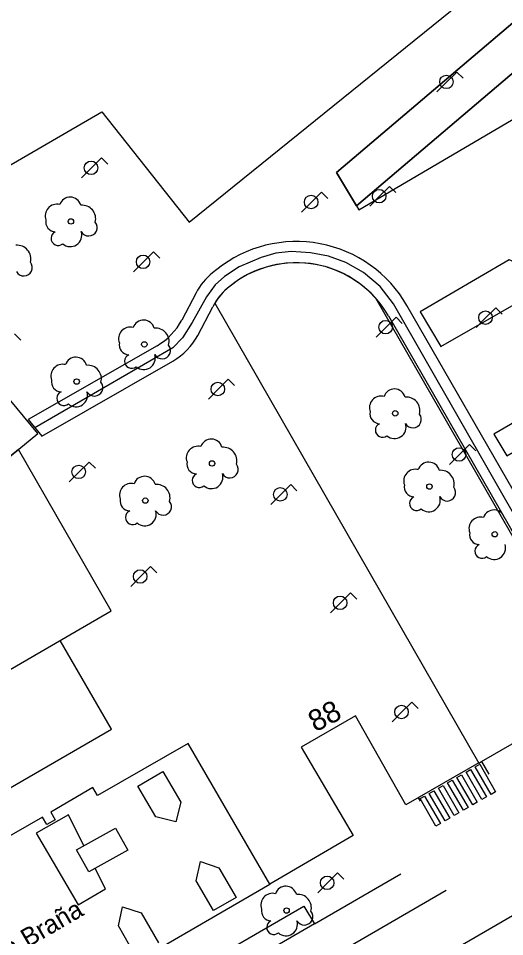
# Model space of a CAD drawing. Extents: x 282771 to 285132, y 4823109 to 4825496.
# Drawn here: x 283637.2 to 283683, y 4823709.7 to 4823796.3 of the extents above; entities that cross this region are included whole.
import ezdxf

# ---------------------------------------------------------------- set-up
doc = ezdxf.new("R2010")
doc.units = 0
for name, color, linetype in [('ACERA-BORDILLO', 7, 'Continuous'), ('ACERA-INTERIOR', 7, 'Continuous'), ('ARBOL', 7, 'Continuous'), ('CALLE-EJE', 7, 'Continuous'), ('CARRIL-BICI-AREA', 7, 'Continuous'), ('CARRIL-BICI-EJE', 7, 'Continuous'), ('EDIFICIO', 7, 'Continuous'), ('FAROLA', 7, 'Continuous'), ('MEDIANERA', 7, 'Continuous'), ('NUM-VADO', 7, 'Continuous'), ('PASO-PEATONES', 7, 'Continuous'), ('PUENTE', 7, 'Continuous'), ('SENAL-VIARIA', 7, 'Continuous'), ('TXT-EDIFICIOS', 7, 'Continuous'), ('ZONA-VERDE', 7, 'Continuous')]:
    doc.layers.add(name, color=color, linetype=linetype)

msp = doc.modelspace()

# ---------------------------------------------------------------- linework, layer by layer
at = {"layer": 'ACERA-BORDILLO'}
for points in [[(283680.803, 4823726.257), (283681.498, 4823725.059)], [(283674.845, 4823722.833), (283675.032, 4823722.51)], [(283440.639, 4823580.325), (283442.766, 4823581.559), (283443.123, 4823584.197), (283443.551, 4823584.826), (283531.38, 4823635.754), (283532.587, 4823633.905), (283540.184, 4823638.45), (283540.235, 4823640.838), (283664.058, 4823712.607), (283665.078, 4823710.943), (283673.217, 4823715.676)]]:
    msp.add_lwpolyline(points, dxfattribs=at)
at = {"layer": 'ACERA-INTERIOR'}
for points in [[(283604.679, 4823764.091), (283645.045, 4823787.52), (283653.258, 4823777.124), (283681.308, 4823799.827), (283702.664, 4823818.433), (283714.124, 4823828.582), (283725.715, 4823837.783), (283799.695, 4823901.125), (283801.01, 4823899.667), (283806.646, 4823904.515), (283805.178, 4823906.015), (283808.042, 4823908.37), (283805.528, 4823911.212), (283808.053, 4823913.515), (283807.084, 4823914.515), (283815.151, 4823921.216), (283815.364, 4823921.378), (283815.599, 4823921.524), (283815.853, 4823921.652), (283816.126, 4823921.757), (283816.413, 4823921.836), (283812.586, 4823926.094)], [(283606.699, 4823706.576), (283645.96, 4823729.307), (283641.115, 4823737.675)], [(283680.564, 4823726.129), (283673.691, 4823722.168), (283668.944, 4823730.574), (283663.817, 4823727.62), (283668.713, 4823719.274), (283660.862, 4823714.71)]]:
    msp.add_lwpolyline(points, dxfattribs=at)
at = {"layer": 'ARBOL'}
for centre in [(283642.123, 4823777.193), (283649.041, 4823765.603), (283642.663, 4823762.099), (283672.676, 4823759.099), (283655.42, 4823754.372), (283675.902, 4823752.197), (283649.131, 4823750.869), (283682.054, 4823747.695), (283662.444, 4823712.205)]:
    msp.add_circle(centre, 0.255, dxfattribs=at)
for centre, radius, start, end in [((283642.053, 4823778.453), 1.038, 15.64225, 161.38431), ((283640.793, 4823777.723), 1.097, 75.43176, 200.55605), ((283643.183, 4823777.453), 1.272, 345.0327, 95.79922), ((283640.683, 4823777.153), 0.935, 168.59894, 268.13232), ((283643.793, 4823776.623), 0.797, 208.96243, 38.99099), ((283640.923, 4823775.603), 0.672, 113.73669, 309.47246), ((283642.063, 4823775.903), 1.086, 228.95444, 17.92792), ((283637.074, 4823773.679), 1.272, 345.0327, 95.79922), ((283637.684, 4823772.849), 0.797, 208.96243, 38.99099), ((283648.971, 4823766.863), 1.038, 15.64225, 161.38431), ((283647.711, 4823766.133), 1.097, 75.43176, 200.55605), ((283650.101, 4823765.863), 1.272, 345.0327, 95.79922), ((283647.601, 4823765.563), 0.935, 168.59894, 268.13232), ((283650.711, 4823765.033), 0.797, 208.96243, 38.99099), ((283642.593, 4823763.359), 1.038, 15.64225, 161.38431), ((283647.841, 4823764.013), 0.672, 113.73669, 309.47246), ((283648.981, 4823764.313), 1.086, 228.95444, 17.92792), ((283641.333, 4823762.629), 1.097, 75.43176, 200.55605), ((283643.723, 4823762.359), 1.272, 345.0327, 95.79922), ((283641.223, 4823762.059), 0.935, 168.59894, 268.13232), ((283644.333, 4823761.529), 0.797, 208.96243, 38.99099), ((283672.606, 4823760.359), 1.038, 15.64225, 161.38431), ((283641.463, 4823760.509), 0.672, 113.73669, 309.47246), ((283642.603, 4823760.809), 1.086, 228.95444, 17.92792), ((283671.346, 4823759.629), 1.097, 75.43176, 200.55605), ((283673.736, 4823759.359), 1.272, 345.0327, 95.79922), ((283671.236, 4823759.059), 0.935, 168.59894, 268.13232), ((283674.346, 4823758.529), 0.797, 208.96243, 38.99099), ((283671.476, 4823757.509), 0.672, 113.73669, 309.47246), ((283672.616, 4823757.809), 1.086, 228.95444, 17.92792), ((283655.35, 4823755.632), 1.038, 15.64225, 161.38431), ((283654.09, 4823754.902), 1.097, 75.43176, 200.55605), ((283656.48, 4823754.632), 1.272, 345.0327, 95.79922), ((283653.98, 4823754.332), 0.935, 168.59894, 268.13232), ((283657.09, 4823753.802), 0.797, 208.96243, 38.99099), ((283675.832, 4823753.457), 1.038, 15.64225, 161.38431), ((283655.36, 4823753.082), 1.086, 228.95444, 17.92792), ((283674.572, 4823752.727), 1.097, 75.43176, 200.55605), ((283676.962, 4823752.457), 1.272, 345.0327, 95.79922), ((283649.061, 4823752.129), 1.038, 15.64225, 161.38431), ((283654.22, 4823752.782), 0.672, 113.73669, 309.47246), ((283647.801, 4823751.399), 1.097, 75.43176, 200.55605), ((283650.191, 4823751.129), 1.272, 345.0327, 95.79922), ((283674.462, 4823752.157), 0.935, 168.59894, 268.13232), ((283677.572, 4823751.627), 0.797, 208.96243, 38.99099), ((283647.691, 4823750.829), 0.935, 168.59894, 268.13232), ((283674.702, 4823750.607), 0.672, 113.73669, 309.47246), ((283675.842, 4823750.907), 1.086, 228.95444, 17.92792), ((283650.801, 4823750.299), 0.797, 208.96243, 38.99099), ((283681.984, 4823748.955), 1.038, 15.64225, 161.38431), ((283647.931, 4823749.279), 0.672, 113.73669, 309.47246), ((283649.071, 4823749.579), 1.086, 228.95444, 17.92792), ((283680.724, 4823748.225), 1.097, 75.43176, 200.55605), ((283680.614, 4823747.655), 0.935, 168.59894, 268.13232), ((283680.854, 4823746.105), 0.672, 113.73669, 309.47246), ((283681.994, 4823746.405), 1.086, 228.95444, 17.92792), ((283662.374, 4823713.465), 1.038, 15.64228, 161.38435), ((283661.114, 4823712.735), 1.097, 75.4318, 200.55608), ((283663.504, 4823712.465), 1.272, 345.03273, 95.79925), ((283661.004, 4823712.165), 0.935, 168.59898, 268.13236), ((283664.114, 4823711.635), 0.797, 208.96246, 38.99103), ((283661.244, 4823710.615), 0.672, 113.73672, 309.4725), ((283662.384, 4823710.915), 1.086, 228.95447, 17.92796)]:
    msp.add_arc(centre, radius, start, end, dxfattribs=at)
at = {"layer": 'CALLE-EJE'}
msp.add_lwpolyline([(283529.623, 4823622.259), (283685.293, 4823712.647)], dxfattribs=at)
at = {"layer": 'CARRIL-BICI-AREA'}
for p, q in [((283655.867, 4823772.67), (283655.472, 4823772.352)), ((283653.909, 4823770.455), (283652.569, 4823767.897)), ((283654.07, 4823766.452), (283655.487, 4823769.157)), ((283696.721, 4823729.269), (283673.783, 4823769.275)), ((283672.048, 4823768.28), (283694.991, 4823728.265)), ((283650.239, 4823765.477), (283638.082, 4823758.507)), ((283639.373, 4823756.941), (283651.74, 4823764.032)), ((283638.082, 4823758.507), (283639.373, 4823756.941))]:
    msp.add_line(p, q, dxfattribs=at)
msp.add_lwpolyline([(283657.049, 4823771.053), (283657.118, 4823771.109)], dxfattribs=at)
for centre, radius, start, end in [((283663.372, 4823763.306), 12, 29.82884, 128.71301), ((283663.372, 4823763.306), 10, 29.82884, 128.71301), ((283659.224, 4823767.671), 6, 128.71301, 152.3451), ((283660.801, 4823766.372), 6, 128.71301, 152.3451), ((283647.254, 4823770.682), 6, 299.8288, 332.3451), ((283648.755, 4823769.237), 6, 299.8288, 332.3451)]:
    msp.add_arc(centre, radius, start, end, dxfattribs=at)
at = {"layer": 'CARRIL-BICI-EJE'}
msp.add_lwpolyline([(283706.223, 4823710.47), (283672.517, 4823769.438), (283671.255, 4823771.052), (283669.683, 4823772.367), (283668.028, 4823773.312), (283666.405, 4823773.92), (283664.701, 4823774.239), (283662.886, 4823774.376), (283661.438, 4823774.202), (283660.033, 4823773.811), (283657.989, 4823772.922), (283656.6, 4823772.005), (283655.722, 4823771.223), (283654.884, 4823770.093), (283653.543, 4823767.672), (283652.632, 4823766.219), (283651.712, 4823765.287), (283638.727, 4823757.725)], dxfattribs=at)
at = {"layer": 'EDIFICIO'}
msp.add_lwpolyline([(283604.186, 4823681.769), (283660.862, 4823714.71), (283653.184, 4823727.954), (283644.633, 4823723.051), (283644.203, 4823723.801), (283640.223, 4823721.481), (283640.643, 4823720.761), (283639.843, 4823720.311), (283639.443, 4823721.021), (283635.463, 4823718.731)], dxfattribs=at)
at = {"layer": 'FAROLA'}
for p, q in [((283678.483, 4823791.287), (283677.543, 4823790.357)), ((283679.073, 4823790.697), (283678.483, 4823791.287)), ((283677.543, 4823790.357), (283676.613, 4823789.417)), ((283645.002, 4823783.186), (283644.062, 4823782.256)), ((283645.592, 4823782.596), (283645.002, 4823783.186)), ((283644.062, 4823782.256), (283643.132, 4823781.316)), ((283672.143, 4823780.507), (283671.203, 4823779.577)), ((283672.733, 4823779.917), (283672.143, 4823780.507)), ((283665.733, 4823779.957), (283664.793, 4823779.027)), ((283666.323, 4823779.367), (283665.733, 4823779.957)), ((283671.203, 4823779.577), (283670.273, 4823778.637)), ((283664.793, 4823779.027), (283663.863, 4823778.087)), ((283649.903, 4823774.317), (283648.963, 4823773.387)), ((283650.493, 4823773.727), (283649.903, 4823774.317)), ((283648.963, 4823773.387), (283648.033, 4823772.447)), ((283682.163, 4823769.057), (283681.223, 4823768.127)), ((283682.753, 4823768.467), (283682.163, 4823769.057)), ((283672.753, 4823768.157), (283671.813, 4823767.227)), ((283673.343, 4823767.567), (283672.753, 4823768.157)), ((283681.223, 4823768.127), (283680.293, 4823767.187)), ((283637.403, 4823766.007), (283636.813, 4823766.597)), ((283671.813, 4823767.227), (283670.883, 4823766.287)), ((283656.942, 4823762.318), (283656.002, 4823761.388)), ((283657.532, 4823761.728), (283656.942, 4823762.318)), ((283656.002, 4823761.388), (283655.072, 4823760.448)), ((283679.673, 4823756.147), (283678.733, 4823755.217)), ((283680.263, 4823755.557), (283679.673, 4823756.147)), ((283678.733, 4823755.217), (283677.803, 4823754.277)), ((283643.833, 4823754.507), (283642.893, 4823753.577)), ((283644.423, 4823753.917), (283643.833, 4823754.507)), ((283642.893, 4823753.577), (283641.963, 4823752.637)), ((283662.833, 4823752.384), (283661.893, 4823751.454)), ((283663.423, 4823751.794), (283662.833, 4823752.384)), ((283661.893, 4823751.454), (283660.963, 4823750.514)), ((283649.623, 4823744.647), (283648.683, 4823743.717)), ((283650.213, 4823744.057), (283649.623, 4823744.647)), ((283648.683, 4823743.717), (283647.753, 4823742.777)), ((283668.465, 4823742.159), (283667.525, 4823741.229)), ((283669.055, 4823741.569), (283668.465, 4823742.159)), ((283667.525, 4823741.229), (283666.595, 4823740.289)), ((283674.252, 4823731.866), (283673.312, 4823730.936)), ((283674.842, 4823731.276), (283674.252, 4823731.866)), ((283673.312, 4823730.936), (283672.382, 4823729.996)), ((283667.249, 4823715.75), (283666.309, 4823714.82)), ((283667.839, 4823715.16), (283667.249, 4823715.75)), ((283666.309, 4823714.82), (283665.379, 4823713.88))]:
    msp.add_line(p, q, dxfattribs=at)
for centre in [(283677.503, 4823790.357), (283644.022, 4823782.256), (283664.753, 4823779.027), (283671.163, 4823779.577), (283648.923, 4823773.387), (283681.183, 4823768.127), (283671.773, 4823767.227), (283655.962, 4823761.388), (283678.693, 4823755.217), (283642.853, 4823753.577), (283661.853, 4823751.454), (283648.643, 4823743.717), (283667.485, 4823741.229), (283673.272, 4823730.936), (283666.269, 4823714.82)]:
    msp.add_circle(centre, 0.637, dxfattribs=at)
at = {"layer": 'MEDIANERA'}
for points in [[(283648.423, 4823723.931), (283650.783, 4823725.311)], [(283650.783, 4823725.311), (283652.473, 4823722.421)], [(283650.113, 4823721.041), (283648.423, 4823723.931)], [(283652.473, 4823722.421), (283652.023, 4823720.561)], [(283641.903, 4823721.241), (283638.863, 4823719.501)], [(283643.353, 4823718.311), (283641.903, 4823721.241)], [(283652.023, 4823720.561), (283650.113, 4823721.041)], [(283642.653, 4823717.921), (283646.333, 4823719.971)], [(283646.333, 4823719.971), (283647.483, 4823717.901)], [(283638.863, 4823719.501), (283642.803, 4823712.761)], [(283643.803, 4823715.851), (283642.653, 4823717.921)], [(283647.483, 4823717.901), (283643.803, 4823715.851)], [(283645.373, 4823714.271), (283644.413, 4823716.181)], [(283653.933, 4823715.021), (283654.323, 4823716.831)], [(283654.323, 4823716.831), (283656.073, 4823716.251)], [(283656.073, 4823716.251), (283657.693, 4823713.431)], [(283655.553, 4823712.201), (283653.933, 4823715.021)], [(283642.803, 4823712.761), (283645.373, 4823714.271)], [(283657.693, 4823713.431), (283655.553, 4823712.201)], [(283646.602, 4823710.751), (283646.993, 4823712.561)], [(283646.993, 4823712.561), (283648.743, 4823711.981)], [(283648.743, 4823711.981), (283650.362, 4823709.161)], [(283648.222, 4823707.931), (283646.602, 4823710.751)]]:
    msp.add_lwpolyline(points, dxfattribs=at)
at = {"layer": 'PASO-PEATONES'}
for points in [[(283680.639, 4823725.999), (283682.137, 4823723.414), (283681.708, 4823723.168), (283680.217, 4823725.756)], [(283678.917, 4823725.007), (283680.408, 4823722.419), (283679.975, 4823722.169), (283678.484, 4823724.758)], [(283679.783, 4823725.507), (283681.275, 4823722.918), (283680.842, 4823722.668), (283679.35, 4823725.257)], [(283677.184, 4823724.009), (283678.676, 4823721.42), (283678.242, 4823721.17), (283676.751, 4823723.759)], [(283678.05, 4823724.508), (283679.542, 4823721.919), (283679.109, 4823721.67), (283677.617, 4823724.258)], [(283676.317, 4823723.509), (283677.809, 4823720.921), (283677.376, 4823720.671), (283675.884, 4823723.26)], [(283675.451, 4823723.01), (283676.943, 4823720.421), (283676.51, 4823720.172), (283675.018, 4823722.761)]]:
    msp.add_lwpolyline(points, close=True, dxfattribs=at)
at = {"layer": 'PUENTE'}
for points in [[(283489.806, 4823867.849), (283499.399, 4823875.506), (283501.814, 4823877.505), (283502.692, 4823877.819), (283504.009, 4823878.038), (283505.702, 4823877.694), (283507.238, 4823877.004), (283513.571, 4823871.298), (283619.822, 4823741.375), (283639.011, 4823757.192)], [(283639.011, 4823757.192), (283635.708, 4823761.198), (283618.458, 4823746.979)]]:
    msp.add_lwpolyline(points, dxfattribs=at)
at = {"layer": 'SENAL-VIARIA'}
for points in [[(283541.02, 4823634.87), (283677.466, 4823714.127)], [(283665.078, 4823710.943), (283604.858, 4823675.953), (283603.92, 4823677.758)]]:
    msp.add_lwpolyline(points, dxfattribs=at)
at = {"layer": 'ZONA-VERDE'}
for p, q in [((283657.118, 4823771.109), (283657.049, 4823771.053)), ((283692.159, 4823732.803), (283670.884, 4823769.907)), ((283655.679, 4823769.497), (283680.554, 4823726.113))]:
    msp.add_line(p, q, dxfattribs=at)
for points in [[(283669.014, 4823778.677), (283667.134, 4823781.802), (283717.422, 4823824.579), (283719.264, 4823821.423)], [(283719.264, 4823821.423), (283717.422, 4823824.579), (283667.134, 4823781.802), (283669.014, 4823778.677)], [(283669.014, 4823778.677), (283692.26, 4823798.469), (283694.106, 4823800.041)], [(283692.26, 4823798.469), (283669.014, 4823778.677), (283669.243, 4823778.296)], [(283669.243, 4823778.296), (283684.171, 4823787.077)], [(283675.039, 4823768.659), (283676.99, 4823765.415), (283687.852, 4823771.621), (283683.401, 4823773.577), (283675.039, 4823768.659)], [(283681.977, 4823757.123), (283683.193, 4823755.102), (283697.913, 4823763.652), (283700.133, 4823759.86), (283704.282, 4823762.194), (283701.872, 4823766.187), (283699.112, 4823767.087), (283681.977, 4823757.123)], [(283637.183, 4823755.686), (283619.822, 4823741.375), (283609.661, 4823753.8), (283598.066, 4823750.886), (283614.627, 4823722.319), (283645.93, 4823740.466), (283637.183, 4823755.686)], [(283680.554, 4823726.113), (283680.803, 4823726.257), (283692.159, 4823732.803)]]:
    msp.add_lwpolyline(points, dxfattribs=at)
for centre, radius, start, end in [((283663.372, 4823763.306), 10, 41.30719, 128.71301), ((283660.801, 4823766.372), 6, 128.71301, 148.61277)]:
    msp.add_arc(centre, radius, start, end, dxfattribs=at)

# ---------------------------------------------------------------- texts
at = {"layer": 'NUM-VADO'}
msp.add_text('88', height=2, rotation=27.45103, dxfattribs=at).set_placement((283665.152, 4823729.004))
at = {"layer": 'TXT-EDIFICIOS'}
msp.add_text('Edificio Prados de La Braña', height=1.75, rotation=30.17571, dxfattribs=at).set_placement((283618.367, 4823697.237))

doc.saveas('drawing.dxf')
